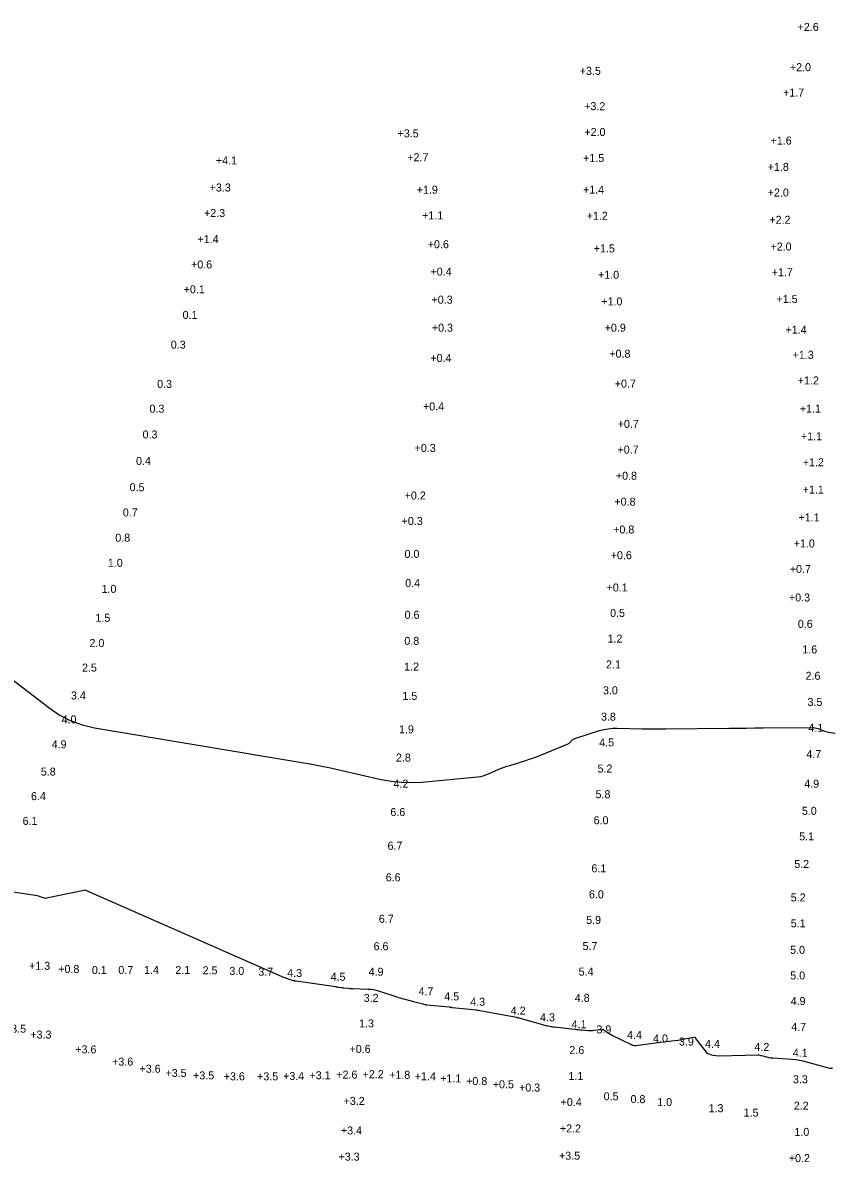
# Model space of a CAD drawing. Extents: x 837127 to 848654, y 3074248 to 3079868.
# Drawn here: x 844520.6 to 844836.9, y 3079092.9 to 3079537.8 of the extents above; entities that cross this region are included whole.
import ezdxf

# ---------------------------------------------------------------- set-up
doc = ezdxf.new("R2010")
doc.units = 0
doc.layers.add('V-HYDS-MAJR', color=7, linetype='Continuous')
doc.layers.add('V-HYDS-SOUN', color=7, linetype='Continuous')

msp = doc.modelspace()

# ---------------------------------------------------------------- linework, layer by layer
at = {"layer": 'V-HYDS-MAJR'}
for points in [[(844511.88, 3079284.96), (844530.7, 3079270.4), (844534.8, 3079267.6), (844539.15, 3079265.36), (844543.74, 3079263.69), (844548.58, 3079262.57), (844628.86, 3079249.1), (844632.86, 3079248.4), (844636.84, 3079247.64), (844640.81, 3079246.83), (844644.77, 3079245.96), (844660.66, 3079242.37), (844664.6, 3079241.64), (844668.55, 3079241.23), (844672.53, 3079241.13), (844676.52, 3079241.35), (844698.33, 3079243.41), (844699.43, 3079243.56), (844700.51, 3079243.79), (844701.56, 3079244.11), (844702.59, 3079244.52), (844706.68, 3079246.31), (844707.71, 3079246.74), (844708.75, 3079247.14), (844709.8, 3079247.52), (844710.86, 3079247.86), (844717.11, 3079249.77), (844718.5, 3079250.22), (844719.88, 3079250.69), (844721.25, 3079251.2), (844722.61, 3079251.73), (844733.05, 3079255.98), (844733.39, 3079256.13), (844733.72, 3079256.32), (844734.02, 3079256.53), (844734.31, 3079256.77), (844735.42, 3079257.79), (844735.71, 3079258.03), (844736.02, 3079258.23), (844736.35, 3079258.4), (844736.7, 3079258.53), (844745.96, 3079261.41), (844747.63, 3079261.86), (844749.32, 3079262.17), (844751.04, 3079262.34), (844752.77, 3079262.37), (844762.81, 3079262.16), (844765.06, 3079262.12), (844767.32, 3079262.1), (844769.57, 3079262.09), (844771.82, 3079262.11), (844796.56, 3079262.36), (844799.92, 3079262.39), (844803.29, 3079262.42), (844806.65, 3079262.45), (844810.01, 3079262.48), (844829.06, 3079262.65), (844829.62, 3079262.63), (844830.17, 3079262.56), (844830.72, 3079262.43), (844831.25, 3079262.26), (844833.36, 3079261.45), (844833.89, 3079261.27), (844834.43, 3079261.1), (844834.98, 3079260.97), (844835.53, 3079260.86), (844838.08, 3079260.42)], [(844837, 3079129.43), (844836.5, 3079129.47), (844836, 3079129.55), (844835.51, 3079129.64), (844835.03, 3079129.76), (844826.93, 3079132), (844825.54, 3079132.34), (844824.15, 3079132.62), (844822.74, 3079132.82), (844821.32, 3079132.95), (844813.71, 3079133.48), (844813.25, 3079133.52), (844812.78, 3079133.58), (844812.32, 3079133.67), (844811.86, 3079133.77), (844809.35, 3079134.39), (844809.24, 3079134.42), (844809.12, 3079134.45), (844809, 3079134.48), (844808.89, 3079134.51), (844808.43, 3079134.64), (844808.31, 3079134.66), (844808.19, 3079134.68), (844808.07, 3079134.69), (844807.96, 3079134.7), (844792.61, 3079134.36), (844791.47, 3079134.4), (844790.37, 3079134.57), (844789.28, 3079134.87), (844788.23, 3079135.3), (844783.58, 3079141.21), (844783.55, 3079141.45), (844783.33, 3079141.57), (844782.94, 3079141.56), (844778.25, 3079140.84), (844778.2, 3079140.83), (844778.15, 3079140.81), (844778.11, 3079140.78), (844778.08, 3079140.75), (844777.94, 3079140.6), (844777.9, 3079140.56), (844777.86, 3079140.54), (844777.81, 3079140.52), (844777.76, 3079140.51), (844771.84, 3079139.86), (844770.83, 3079139.75), (844769.83, 3079139.63), (844768.83, 3079139.5), (844767.83, 3079139.37), (844760.11, 3079138.32), (844759.97, 3079138.31), (844759.83, 3079138.31), (844759.69, 3079138.33), (844759.56, 3079138.36), (844759.01, 3079138.53), (844758.88, 3079138.57), (844758.75, 3079138.62), (844758.61, 3079138.67), (844758.49, 3079138.73), (844750.88, 3079142.38), (844750.5, 3079142.58), (844750.12, 3079142.79), (844749.75, 3079143.01), (844749.39, 3079143.24), (844747.35, 3079144.62), (844747.3, 3079144.64), (844747.24, 3079144.66), (844747.19, 3079144.66), (844747.13, 3079144.65), (844746.89, 3079144.58), (844746.83, 3079144.57), (844746.77, 3079144.56), (844746.71, 3079144.55), (844746.65, 3079144.54), (844743.71, 3079144.28), (844743.2, 3079144.24), (844742.69, 3079144.23), (844742.18, 3079144.23), (844741.67, 3079144.26), (844738.9, 3079144.44), (844738.27, 3079144.49), (844737.63, 3079144.54), (844737, 3079144.6), (844736.37, 3079144.67), (844728.3, 3079145.58), (844728, 3079145.62), (844727.69, 3079145.66), (844727.39, 3079145.71), (844727.09, 3079145.77), (844725.89, 3079146), (844725.59, 3079146.07), (844725.29, 3079146.13), (844724.99, 3079146.21), (844724.7, 3079146.29), (844714.54, 3079149.15), (844714.48, 3079149.17), (844714.43, 3079149.18), (844714.37, 3079149.2), (844714.32, 3079149.21), (844714.08, 3079149.27), (844714.03, 3079149.28), (844713.98, 3079149.3), (844713.93, 3079149.31), (844713.88, 3079149.33), (844713.68, 3079149.39), (844713.63, 3079149.4), (844713.58, 3079149.42), (844713.53, 3079149.43), (844713.47, 3079149.44), (844698.55, 3079152.12), (844698.48, 3079152.14), (844698.4, 3079152.15), (844698.33, 3079152.17), (844698.26, 3079152.19), (844697.99, 3079152.27), (844697.92, 3079152.29), (844697.84, 3079152.3), (844697.77, 3079152.31), (844697.7, 3079152.32), (844688.54, 3079153.19), (844688.43, 3079153.2), (844688.32, 3079153.22), (844688.21, 3079153.24), (844688.1, 3079153.27), (844687.67, 3079153.37), (844687.57, 3079153.4), (844687.46, 3079153.42), (844687.35, 3079153.44), (844687.24, 3079153.45), (844678.54, 3079154.24), (844678.4, 3079154.25), (844678.26, 3079154.28), (844678.12, 3079154.3), (844677.99, 3079154.34), (844677.45, 3079154.48), (844677.31, 3079154.52), (844677.17, 3079154.56), (844677.04, 3079154.59), (844676.9, 3079154.63), (844674.33, 3079155.26), (844673.85, 3079155.37), (844673.38, 3079155.49), (844672.91, 3079155.62), (844672.43, 3079155.74), (844669.46, 3079156.53), (844668.81, 3079156.7), (844668.16, 3079156.89), (844667.52, 3079157.08), (844666.88, 3079157.29), (844659.76, 3079159.62), (844658.7, 3079159.92), (844657.62, 3079160.15), (844656.53, 3079160.3), (844655.43, 3079160.38), (844649.59, 3079160.56), (844649.19, 3079160.58), (844648.78, 3079160.6), (844648.38, 3079160.63), (844647.97, 3079160.67), (844646.08, 3079160.87), (844645.81, 3079160.9), (844645.55, 3079160.93), (844645.28, 3079160.96), (844645.02, 3079161), (844643.96, 3079161.16), (844643.7, 3079161.2), (844643.43, 3079161.24), (844643.17, 3079161.28), (844642.9, 3079161.32), (844627.41, 3079163.6), (844627.36, 3079163.6), (844627.3, 3079163.61), (844627.25, 3079163.62), (844627.2, 3079163.62), (844626.97, 3079163.65), (844626.93, 3079163.66), (844626.88, 3079163.66), (844626.83, 3079163.66), (844626.78, 3079163.67), (844626.58, 3079163.67), (844626.54, 3079163.68), (844626.49, 3079163.68), (844626.44, 3079163.69), (844626.39, 3079163.71), (844622.17, 3079165.14), (844621.74, 3079165.35), (844544.89, 3079199.09), (844544.43, 3079198.94), (844529.87, 3079195.94), (844529.4, 3079195.92), (844528.9, 3079196.02), (844526.75, 3079196.72), (844526.3, 3079196.88), (844516.82, 3079198.29)]]:
    msp.add_lwpolyline(points, dxfattribs=at)

# ---------------------------------------------------------------- texts
at = {"layer": 'V-HYDS-SOUN'}
for s, p in [('+2.6 ', (844823.38, 3079534.64)), ('+2.0 ', (844820.35, 3079518.92)), ('+3.5 ', (844738.24, 3079517.48)), ('+1.7 ', (844817.68, 3079509)), ('+3.2 ', (844739.97, 3079503.69)), ('+3.5 ', (844667.04, 3079493.07)), ('+2.0 ', (844740.04, 3079493.62)), ('+1.6 ', (844812.82, 3079490.26)), ('+4.1 ', (844596.06, 3079482.5)), ('+2.7 ', (844670.85, 3079483.76)), ('+1.5 ', (844739.53, 3079483.43)), ('+1.8 ', (844811.69, 3079479.99)), ('+3.3 ', (844593.6, 3079471.93)), ('+1.9 ', (844674.52, 3079471.07)), ('+1.4 ', (844739.51, 3079471.08)), ('+2.0 ', (844811.7, 3079469.98)), ('+2.3 ', (844591.41, 3079461.98)), ('+1.1 ', (844676.63, 3079461.03)), ('+1.2 ', (844740.97, 3079460.88)), ('+2.2 ', (844812.34, 3079459.33)), ('+1.4 ', (844588.85, 3079451.79)), ('+0.6 ', (844678.83, 3079449.78)), ('+1.5 ', (844743.68, 3079448.15)), ('+2.0 ', (844812.77, 3079448.87)), ('+0.6 ', (844586.34, 3079441.88)), ('+0.4 ', (844679.91, 3079439.08)), ('+1.7 ', (844813.26, 3079438.86)), ('+1.0 ', (844745.4, 3079437.86)), ('+0.1 ', (844583.46, 3079432.18)), ('+0.3 ', (844680.31, 3079428.14)), ('+1.0 ', (844746.66, 3079427.44)), ('+1.5 ', (844815.14, 3079428.42)), ('0.1', (844583.02, 3079422.19)), ('+0.3 ', (844680.44, 3079417.18)), ('+0.9 ', (844747.99, 3079417.2)), ('+1.4 ', (844818.65, 3079416.41)), ('0.3', (844578.42, 3079410.58)), ('+0.8 ', (844749.8, 3079407.04)), ('+0.4 ', (844679.87, 3079405.36)), ('+1.3 ', (844821.42, 3079406.6)), ('0.3', (844573.07, 3079395.25)), ('+0.7 ', (844751.92, 3079395.35)), ('+1.2 ', (844823.44, 3079396.59)), ('0.3', (844570.09, 3079385.57)), ('+0.4 ', (844676.98, 3079386.46)), ('+1.1 ', (844824.24, 3079385.59)), ('+0.7 ', (844753.08, 3079379.64)), ('0.3', (844567.39, 3079375.5)), ('+1.1 ', (844824.68, 3079374.83)), ('+0.3 ', (844673.71, 3079370.24)), ('+0.7 ', (844753, 3079369.58)), ('0.4', (844564.83, 3079365.16)), ('+1.2 ', (844825.4, 3079364.66)), ('+0.8 ', (844752.36, 3079359.38)), ('0.5', (844562.32, 3079354.89)), ('+1.1 ', (844825.37, 3079353.98)), ('+0.2 ', (844669.81, 3079351.67)), ('+0.8 ', (844751.79, 3079349.27)), ('0.7', (844559.68, 3079345.03)), ('+0.3 ', (844668.62, 3079341.72)), ('+1.1 ', (844823.74, 3079343.11)), ('+0.8 ', (844751.31, 3079338.39)), ('0.8', (844556.74, 3079335.19)), ('+1.0 ', (844821.85, 3079332.93)), (' 0.0', (844668.6, 3079328.87)), ('+0.6 ', (844750.35, 3079328.36)), ('1.0', (844553.82, 3079325.38)), ('+0.7 ', (844820.33, 3079322.97)), ('1.0', (844551.35, 3079315.22)), ('0.4', (844670.03, 3079317.46)), ('+0.1 ', (844748.74, 3079315.75)), ('+0.3 ', (844820, 3079311.84)), ('0.6', (844669.79, 3079305.08)), ('0.5', (844750.1, 3079305.81)), ('1.5', (844548.97, 3079303.92)), ('0.6', (844823.47, 3079301.54)), ('1.2', (844749.11, 3079295.78)), ('2.0', (844546.64, 3079294.05)), ('0.8', (844669.69, 3079294.92)), ('1.6', (844825.22, 3079291.55)), ('2.5', (844543.7, 3079284.47)), ('1.2', (844669.6, 3079284.85)), ('2.1', (844748.5, 3079285.7)), ('2.6', (844826.49, 3079281.27)), ('3.4', (844539.41, 3079273.59)), ('1.5', (844668.94, 3079273.42)), ('3.0', (844747.32, 3079275.59)), ('3.5', (844827.26, 3079271.07)), ('3.8', (844746.54, 3079265.31)), ('4.0', (844535.73, 3079264.24)), ('1.9', (844667.61, 3079260.38)), ('4.1', (844827.56, 3079260.98)), ('4.9', (844531.87, 3079254.52)), ('4.5', (844745.85, 3079255.28)), ('2.8', (844666.41, 3079249.35)), ('4.7', (844826.81, 3079250.69)), ('5.8', (844527.62, 3079243.86)), ('5.2', (844745.18, 3079245.06)), ('4.2', (844665.45, 3079239.14)), ('4.9', (844825.98, 3079239.12)), ('6.4', (844523.78, 3079234.28)), ('5.8', (844744.41, 3079235.03)), ('6.1', (844520.5, 3079224.61)), ('6.6', (844664.23, 3079228.06)), ('6.0', (844743.67, 3079224.86)), ('5.0', (844825.04, 3079228.55)), ('5.1', (844823.99, 3079218.57)), ('6.7', (844663.12, 3079214.91)), ('5.2', (844822.08, 3079207.78)), ('6.6', (844662.42, 3079202.56)), ('6.1', (844742.8, 3079206.08)), ('6.0', (844741.84, 3079195.94)), ('5.2', (844820.7, 3079194.72)), ('6.7', (844659.72, 3079186.37)), ('5.9', (844740.75, 3079185.96)), ('5.1', (844820.7, 3079184.62)), ('6.6', (844657.67, 3079175.66)), ('5.7', (844739.34, 3079175.76)), ('5.0', (844820.46, 3079174.27)), ('+1.3 ', (844523.03, 3079168.02)), ('+0.8 ', (844534.44, 3079166.78)), ('0.1', (844547.58, 3079166.38)), ('0.7', (844557.93, 3079166.39)), ('1.4', (844567.97, 3079166.44)), ('2.1', (844580.19, 3079166.4)), ('2.5', (844590.85, 3079166.26)), ('3.0', (844601.31, 3079166.03)), ('3.7', (844612.62, 3079165.71)), ('4.3', (844623.92, 3079165.23)), ('4.5', (844640.86, 3079163.77)), ('4.9', (844655.74, 3079165.71)), ('5.4', (844737.82, 3079165.77)), ('5.0', (844820.52, 3079164.26)), ('4.7', (844675.23, 3079158.07)), ('3.2', (844653.81, 3079155.5)), ('4.5', (844685.29, 3079156.07)), ('4.3', (844695.43, 3079153.97)), ('4.8', (844736.3, 3079155.51)), ('4.9', (844820.67, 3079154.26)), ('4.2', (844711.26, 3079150.52)), ('1.3', (844652, 3079145.54)), ('4.3', (844722.74, 3079147.91)), ('4.1', (844735.04, 3079145.2)), ('+3.5 ', (844513.61, 3079143.46)), ('+3.3 ', (844523.53, 3079141.18)), ('3.9', (844744.77, 3079143.18)), ('4.4', (844756.75, 3079141.07)), ('4.7', (844820.91, 3079144.17)), ('+3.6 ', (844541.09, 3079135.4)), ('+0.6 ', (844648.27, 3079135.58)), ('4.0', (844766.9, 3079139.64)), ('3.9', (844777.02, 3079138.45)), ('4.4', (844787.2, 3079137.55)), ('4.2', (844806.51, 3079136.35)), ('2.6', (844734.19, 3079135.12)), ('4.1', (844821.5, 3079134.05)), ('+3.6 ', (844555.48, 3079130.62)), ('+3.6 ', (844566.2, 3079127.83)), ('+3.5 ', (844576.34, 3079126.2)), ('+3.5 ', (844587.12, 3079125.23)), ('+3.6 ', (844599.1, 3079124.86)), ('+3.5 ', (844612.14, 3079124.86)), ('+3.4 ', (844622.29, 3079125)), ('+3.1 ', (844632.62, 3079125.29)), ('+2.6 ', (844643.1, 3079125.54)), ('+2.2 ', (844653.37, 3079125.69)), ('+1.8 ', (844663.74, 3079125.46)), ('+1.4 ', (844673.76, 3079124.9)), ('+1.1 ', (844683.68, 3079124.06)), ('+0.8 ', (844693.84, 3079123.01)), ('1.1', (844733.82, 3079125.03)), ('3.3', (844821.55, 3079123.72)), ('+0.5 ', (844704.25, 3079121.76)), ('+0.3 ', (844714.52, 3079120.48)), ('+3.2 ', (844645.97, 3079115.28)), ('+0.4 ', (844730.77, 3079114.84)), ('0.5', (844747.58, 3079117.07)), ('0.8', (844758.09, 3079115.97)), ('1.0', (844768.51, 3079114.81)), ('2.2', (844821.9, 3079113.41)), ('1.3', (844788.59, 3079112.43)), ('1.5', (844802.28, 3079110.69)), ('+2.2 ', (844730.47, 3079104.52)), ('+3.4 ', (844644.9, 3079103.74)), ('1.0', (844822.13, 3079103.18)), ('+3.3 ', (844643.96, 3079093.51)), ('+3.5 ', (844730.14, 3079093.87)), ('+0.2 ', (844819.94, 3079092.94))]:
    msp.add_text(s, height=3.125, dxfattribs=at).set_placement(p)

doc.saveas('drawing.dxf')
